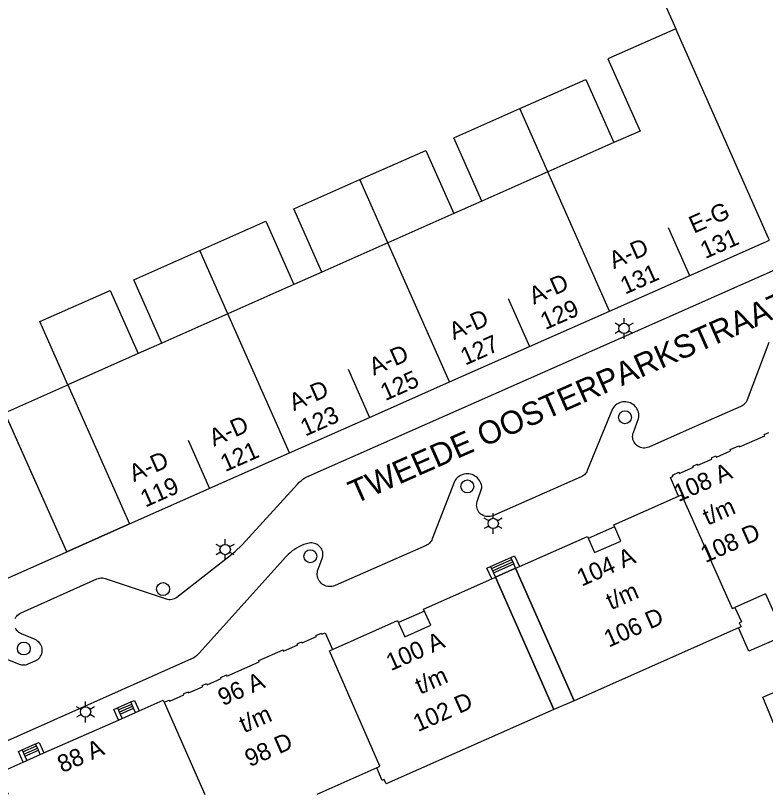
# Model space of a CAD drawing. Extents: x 122462 to 123306, y 485548 to 486417.
# Drawn here: x 122932.7 to 122997.6, y 485548.3 to 485615.8 of the extents above; entities that cross this region are included whole.
import ezdxf

# ---------------------------------------------------------------- set-up
doc = ezdxf.new("R2010")
doc.units = 0
for name, color, linetype in [('B-WE-IE-MEUBILAIR_WEGMEUBILAIR_VERKEERSBORD-S', 7, 'Continuous'), ('Level 1', 7, 'Continuous'), ('Level 10', 7, 'Continuous'), ('Level 11', 7, 'Continuous'), ('Level 17', 7, 'Continuous'), ('Level 19', 7, 'Continuous'), ('Level 21', 7, 'Continuous'), ('Level 30', 7, 'Continuous'), ('Level 31', 7, 'Continuous'), ('Level 33', 7, 'Continuous'), ('Level 4', 7, 'Continuous'), ('Level 50', 7, 'Continuous'), ('Level 53', 7, 'Continuous'), ('N werkgrens', 7, 'Continuous'), ('N-WE-AL-T25', 7, 'Continuous'), ('N-WE-GR-BOOM_DOORWORTELBARE RUIMTE-G', 7, 'Continuous')]:
    doc.layers.add(name, color=color, linetype=linetype)

msp = doc.modelspace()

# ---------------------------------------------------------------- linework, layer by layer
at = {"layer": 'Level 1'}
for p, q in [((122984.506, 485604.819), (122978.793, 485602.284)), ((122978.793, 485602.284), (122973.081, 485599.749)), ((122973.081, 485599.749), (122970.643, 485598.667)), ((122970.643, 485598.667), (122964.93, 485596.132)), ((122964.93, 485596.132), (122959.218, 485593.597)), ((122959.218, 485593.597), (122956.78, 485592.515)), ((122956.78, 485592.515), (122951.067, 485589.98)), ((122937.1, 485569.36), (122927.164, 485591.602)), ((122977.213, 485587.149), (122984.146, 485590.223)), ((122951.067, 485589.98), (122945.355, 485587.445)), ((122945.355, 485587.445), (122943.29, 485586.528)), ((122970.281, 485584.075), (122977.213, 485587.149)), ((122943.29, 485586.528), (122937.204, 485583.828)), ((122963.348, 485581), (122970.281, 485584.075)), ((122937.204, 485583.828), (122942.551, 485571.778)), ((122956.416, 485577.926), (122963.348, 485581)), ((122942.551, 485571.778), (122956.416, 485577.926)), ((122976.004, 485567.929), (122976.324, 485568.071)), ((122973.927, 485567.007), (122974.246, 485567.148)), ((122997.667, 485565.71), (122995.013, 485564.536)), ((122941.573, 485554.763), (122941.895, 485554.905)), ((122941.895, 485554.905), (122943.056, 485555.417)), ((122943.056, 485555.417), (122943.376, 485555.558)), ((122935.122, 485551.92), (122941.573, 485554.763)), ((122933.632, 485551.263), (122934.802, 485551.779)), ((122934.802, 485551.779), (122935.122, 485551.92)), ((122933.311, 485551.122), (122933.632, 485551.263)), ((122963.964, 485550.622), (122958.766, 485548.322))]:
    msp.add_line(p, q, dxfattribs=at)
for points in [[(122990.902, 485617.994), (122988.827, 485617.071), (122989.883, 485614.69)], [(122989.883, 485614.69), (122984.006, 485612.082), (122986.781, 485605.829), (122984.506, 485604.819)], [(122984.146, 485590.223), (122987.657, 485591.78), (122998.009, 485596.37), (122997.93, 485596.553)], [(122915.14, 485586.229), (122925.07, 485563.999), (122937.1, 485569.36)], [(122990.12, 485574.189), (122989.41, 485575.799), (122989.655, 485575.91), (122989.61, 485576.009), (122990.143, 485576.246), (122990.187, 485576.146), (122991.414, 485576.688), (122991.37, 485576.788), (122991.745, 485576.954), (122991.789, 485576.853), (122993.016, 485577.395), (122992.972, 485577.496), (122993.366, 485577.67), (122993.41, 485577.569), (122994.632, 485578.109), (122994.588, 485578.21), (122995.357, 485578.55), (122995.401, 485578.449), (122997.588, 485579.415), (122997.544, 485579.516), (122997.939, 485579.689)], [(122976.324, 485568.071), (122982.222, 485570.687), (122982.847, 485569.28), (122985.12, 485570.288), (122984.499, 485571.679), (122990.12, 485574.189)], [(122995.326, 485562.749), (122981.084, 485556.447), (122976.004, 485567.929)], [(122974.246, 485567.148), (122979.325, 485555.669), (122964.777, 485549.232), (122964.607, 485549.616), (122964.442, 485549.543), (122963.964, 485550.622)], [(122960.142, 485560.892), (122965.775, 485563.39), (122966.391, 485561.989), (122968.651, 485562.982), (122968.029, 485564.39), (122973.927, 485567.007)], [(122995.013, 485564.536), (122995.567, 485563.283), (122995.384, 485563.202), (122995.542, 485562.845), (122995.326, 485562.749)], [(122945.548, 485556.308), (122945.989, 485556.502), (122946.033, 485556.402), (122947.26, 485556.943), (122947.216, 485557.043), (122947.605, 485557.214), (122947.649, 485557.114), (122948.876, 485557.654), (122948.832, 485557.755), (122949.217, 485557.925), (122949.261, 485557.825), (122950.492, 485558.367), (122950.448, 485558.468), (122950.943, 485558.686), (122950.987, 485558.586), (122953.789, 485559.821), (122953.745, 485559.92), (122955.855, 485560.85), (122955.899, 485560.75), (122957.118, 485561.287), (122957.074, 485561.387), (122957.467, 485561.56), (122957.511, 485561.461), (122958.733, 485561.999), (122958.689, 485562.099), (122959.17, 485562.309), (122959.215, 485562.211), (122959.509, 485562.34), (122960.142, 485560.892)], [(123003.934, 485554.519), (122999.198, 485552.468), (122997.411, 485556.744), (123001.734, 485558.616)], [(122943.376, 485555.558), (122945.469, 485556.479), (122945.548, 485556.308)], [(122932.05, 485548.322), (122931.219, 485550.199), (122933.311, 485551.122)]]:
    msp.add_lwpolyline(points, dxfattribs=at)
at = {"layer": 'Level 10'}
for points in [[(122937.1, 485569.36), (122931.724, 485581.396), (122937.204, 485583.828), (122942.551, 485571.778), (122937.1, 485569.36)], [(122979.325, 485555.669), (122974.246, 485567.148), (122976.004, 485567.929), (122981.084, 485556.447), (122979.325, 485555.669)]]:
    msp.add_lwpolyline(points, dxfattribs=at)
at = {"layer": 'Level 11'}
for p, q in [((122984.572, 485571.522), (122982.299, 485570.514)), ((122968.107, 485564.218), (122965.848, 485563.225))]:
    msp.add_line(p, q, dxfattribs=at)
at = {"layer": 'Level 17'}
msp.add_line((122937.1, 485569.36), (122942.551, 485571.778), dxfattribs=at)
for points in [[(122940.067, 485567.092), (122940.191, 485567.091), (122940.313, 485567.074), (122940.433, 485567.042), (122945.713, 485565.275), (122945.832, 485565.243), (122945.954, 485565.226), (122946.077, 485565.224), (122946.2, 485565.238), (122946.32, 485565.266), (122946.435, 485565.309), (122946.544, 485565.365), (122946.646, 485565.435), (122951.671, 485569.361), (122952.291, 485569.961), (122957.106, 485575.228), (122957.251, 485575.376), (122957.406, 485575.514), (122957.57, 485575.64), (122957.742, 485575.755), (122957.922, 485575.858), (122958.108, 485575.948), (122988.609, 485589.427), (122998.537, 485593.815)], [(122997.939, 485587.488), (122996.081, 485582.534), (122996.031, 485582.428), (122995.971, 485582.327), (122995.9, 485582.234), (122995.82, 485582.149), (122995.731, 485582.072), (122995.634, 485582.006), (122995.531, 485581.95), (122992.224, 485580.499), (122991.032, 485579.976), (122987.543, 485578.432), (122987.427, 485578.389), (122987.307, 485578.361), (122987.184, 485578.348), (122987.061, 485578.35), (122986.939, 485578.368), (122986.82, 485578.4), (122986.705, 485578.446), (122986.598, 485578.507), (122986.498, 485578.58), (122986.409, 485578.665), (122986.331, 485578.76), (122986.264, 485578.864), (122986.212, 485578.976), (122986.173, 485579.093), (122986.149, 485579.214), (122986.14, 485579.337), (122986.147, 485579.461), (122986.169, 485579.582), (122986.205, 485579.7), (122986.661, 485580.911), (122986.678, 485581.047), (122986.681, 485581.183), (122986.667, 485581.319), (122986.639, 485581.453), (122986.596, 485581.583), (122986.539, 485581.707), (122986.469, 485581.824), (122986.385, 485581.932)], [(122986.385, 485581.932), (122986.291, 485582.031), (122986.185, 485582.118), (122986.071, 485582.193), (122985.949, 485582.255), (122985.821, 485582.302), (122985.689, 485582.336), (122985.553, 485582.354), (122985.417, 485582.357), (122985.28, 485582.345), (122985.147, 485582.317), (122985.017, 485582.275), (122984.892, 485582.219), (122984.775, 485582.149), (122984.666, 485582.067), (122984.567, 485581.972), (122984.479, 485581.868), (122984.403, 485581.754), (122982.209, 485576.391), (122982.162, 485576.292), (122982.104, 485576.199), (122982.037, 485576.113), (122981.96, 485576.034), (122981.875, 485575.965), (122981.784, 485575.905), (122981.686, 485575.855), (122974.028, 485572.484), (122973.914, 485572.442), (122973.795, 485572.414), (122973.674, 485572.4), (122973.552, 485572.402), (122973.431, 485572.418), (122973.313, 485572.449), (122973.199, 485572.494), (122973.092, 485572.553), (122972.993, 485572.624), (122972.904, 485572.706), (122972.825, 485572.799), (122972.757, 485572.901), (122972.703, 485573.01), (122972.663, 485573.125), (122972.636, 485573.245), (122972.625, 485573.366), (122972.628, 485573.488), (122972.646, 485573.608), (122972.679, 485573.726), (122973.081, 485574.891), (122973.068, 485575.029), (122973.04, 485575.164), (122972.998, 485575.295), (122972.941, 485575.421), (122972.872, 485575.541), (122972.789, 485575.652), (122972.696, 485575.753), (122972.591, 485575.844), (122972.478, 485575.922), (122972.357, 485575.988), (122972.229, 485576.041), (122972.096, 485576.079), (122971.96, 485576.103), (122971.822, 485576.111), (122971.684, 485576.105), (122971.548, 485576.084), (122971.414, 485576.048), (122971.286, 485575.998), (122971.163, 485575.934), (122971.048, 485575.857), (122970.943, 485575.768), (122970.847, 485575.669), (122970.763, 485575.559), (122970.691, 485575.441), (122968.775, 485570.465), (122968.729, 485570.363), (122968.671, 485570.266), (122968.603, 485570.176), (122968.525, 485570.095), (122968.439, 485570.023), (122968.345, 485569.961), (122968.245, 485569.91), (122960.352, 485566.431), (122960.231, 485566.386), (122960.105, 485566.355), (122959.976, 485566.34), (122959.847, 485566.339), (122959.718, 485566.354), (122959.592, 485566.384), (122959.471, 485566.429), (122959.355, 485566.487), (122959.247, 485566.559), (122959.149, 485566.642), (122959.061, 485566.737), (122958.984, 485566.842), (122958.921, 485566.955), (122958.871, 485567.074), (122958.835, 485567.198), (122958.814, 485567.326), (122958.809, 485567.456), (122958.819, 485567.585), (122958.843, 485567.712), (122958.883, 485567.835), (122959.24, 485568.759)], [(122959.24, 485568.759), (122959.276, 485568.873), (122959.299, 485568.99), (122959.308, 485569.109), (122959.302, 485569.229), (122959.282, 485569.346), (122959.248, 485569.461), (122959.201, 485569.571), (122959.14, 485569.674), (122959.069, 485569.769), (122958.986, 485569.855), (122958.893, 485569.931), (122958.792, 485569.995), (122958.685, 485570.047), (122958.571, 485570.085), (122958.455, 485570.109), (122958.336, 485570.12), (122958.216, 485570.116), (122958.098, 485570.098), (122957.873, 485570.042), (122957.653, 485569.972), (122957.437, 485569.889), (122957.227, 485569.792), (122957.023, 485569.681), (122956.827, 485569.559), (122956.639, 485569.423), (122956.46, 485569.277), (122956.29, 485569.119), (122956.131, 485568.951), (122948.577, 485560.561), (122948.46, 485560.441), (122948.333, 485560.332), (122948.198, 485560.234), (122948.055, 485560.147), (122947.905, 485560.072), (122926.951, 485550.731)], [(122932.638, 485563.565), (122932.694, 485563.674), (122932.763, 485563.775), (122932.844, 485563.867), (122932.936, 485563.948), (122933.036, 485564.017), (122933.145, 485564.074), (122939.708, 485567.006), (122939.824, 485567.05), (122939.944, 485567.079), (122940.067, 485567.092)], [(122928.201, 485561.532), (122932.979, 485559.619), (122933.085, 485559.583), (122933.195, 485559.56), (122933.307, 485559.549), (122933.419, 485559.55), (122933.53, 485559.564), (122933.639, 485559.59), (122933.745, 485559.628), (122934.374, 485559.898), (122934.484, 485559.953), (122934.586, 485560.022), (122934.68, 485560.103), (122934.762, 485560.194), (122934.833, 485560.295), (122934.891, 485560.404), (122934.935, 485560.519), (122934.964, 485560.639), (122934.979, 485560.761), (122934.978, 485560.884), (122934.962, 485561.007), (122934.931, 485561.126), (122934.886, 485561.241), (122934.827, 485561.349), (122934.755, 485561.449), (122934.672, 485561.54), (122934.578, 485561.619), (122934.475, 485561.687), (122934.364, 485561.741), (122933.17, 485562.238), (122933.06, 485562.292), (122932.957, 485562.358), (122932.864, 485562.437), (122932.78, 485562.527), (122932.708, 485562.626), (122932.649, 485562.733)]]:
    msp.add_lwpolyline(points, dxfattribs=at)
at = {"layer": 'Level 19'}
for p, q in [((122978.793, 485602.284), (122976.359, 485607.769)), ((122964.93, 485596.132), (122962.496, 485601.617)), ((122951.067, 485589.98), (122948.633, 485595.465))]:
    msp.add_line(p, q, dxfattribs=at)
msp.add_lwpolyline([(122997.667, 485565.71), (122999.272, 485562.08), (122996.22, 485560.729), (122995.326, 485562.749)], dxfattribs=at)
at = {"layer": 'Level 21'}
for p, q in [((122975.837, 485568.305), (122975.594, 485568.853)), ((122973.836, 485568.072), (122974.079, 485567.524)), ((122976.004, 485567.929), (122975.837, 485568.305)), ((122974.079, 485567.524), (122974.246, 485567.148)), ((122942.895, 485555.785), (122942.653, 485556.334)), ((122941.491, 485555.821), (122941.733, 485555.272)), ((122943.056, 485555.417), (122942.895, 485555.785)), ((122941.733, 485555.272), (122941.895, 485554.905)), ((122934.64, 485552.146), (122934.398, 485552.695)), ((122933.228, 485552.18), (122933.47, 485551.631)), ((122933.47, 485551.631), (122933.632, 485551.263)), ((122934.802, 485551.779), (122934.64, 485552.146))]:
    msp.add_line(p, q, dxfattribs=at)
for points in [[(122975.594, 485568.853), (122975.914, 485568.995), (122976.324, 485568.071)], [(122973.927, 485567.007), (122973.517, 485567.931), (122973.836, 485568.072)], [(122942.653, 485556.334), (122942.973, 485556.474), (122943.376, 485555.558)], [(122941.573, 485554.763), (122941.17, 485555.679), (122941.491, 485555.821)], [(122934.398, 485552.695), (122934.718, 485552.836), (122935.122, 485551.92)], [(122933.311, 485551.122), (122932.907, 485552.038), (122933.228, 485552.18)]]:
    msp.add_lwpolyline(points, dxfattribs=at)
at = {"layer": 'Level 30'}
for p, q in [((122974.079, 485567.524), (122975.837, 485568.305)), ((122976.004, 485567.929), (122974.246, 485567.148)), ((122941.733, 485555.272), (122942.895, 485555.785)), ((122933.47, 485551.631), (122934.64, 485552.146))]:
    msp.add_line(p, q, dxfattribs=at)
at = {"layer": 'Level 31'}
for p, q in [((122973.836, 485568.072), (122975.594, 485568.853)), ((122941.491, 485555.821), (122942.653, 485556.334)), ((122933.228, 485552.18), (122934.398, 485552.695))]:
    msp.add_line(p, q, dxfattribs=at)
at = {"layer": 'Level 33'}
for p, q in [((122973.913, 485567.899), (122975.671, 485568.68)), ((122973.996, 485567.711), (122975.754, 485568.492)), ((122941.568, 485555.647), (122942.73, 485556.16)), ((122941.65, 485555.46), (122942.812, 485555.973)), ((122933.305, 485552.006), (122934.475, 485552.521)), ((122933.387, 485551.819), (122934.557, 485552.334))]:
    msp.add_line(p, q, dxfattribs=at)
at = {"layer": 'Level 4'}
for p, q in [((122997.93, 485596.553), (122989.883, 485614.69)), ((122984.146, 485590.223), (122978.793, 485602.284)), ((122970.281, 485584.075), (122964.93, 485596.132)), ((122956.416, 485577.926), (122951.067, 485589.98)), ((122945.548, 485556.308), (122949.067, 485548.322))]:
    msp.add_line(p, q, dxfattribs=at)
for points in [[(122990.12, 485574.189), (122990.377, 485574.305), (122994.761, 485564.424), (122995.013, 485564.536)], [(122963.964, 485550.622), (122964.247, 485550.781), (122959.86, 485560.767), (122960.142, 485560.892)]]:
    msp.add_lwpolyline(points, dxfattribs=at)
at = {"layer": 'Level 50'}
for p, q in [((122985.4, 485589.169), (122985.4, 485589.619)), ((122985.01, 485588.944), (122984.62, 485589.169)), ((122986.179, 485589.169), (122985.789, 485588.944)), ((122985.01, 485588.494), (122984.62, 485588.269)), ((122985.4, 485587.819), (122985.4, 485588.269)), ((122986.179, 485588.269), (122985.789, 485588.494)), ((122974.06, 485572.259), (122974.06, 485572.709)), ((122973.67, 485572.034), (122973.28, 485572.259)), ((122974.839, 485572.259), (122974.449, 485572.034)), ((122973.67, 485571.584), (122973.28, 485571.359)), ((122974.06, 485570.909), (122974.06, 485571.359)), ((122974.839, 485571.359), (122974.449, 485571.584)), ((122950.83, 485569.999), (122950.83, 485570.449)), ((122950.44, 485569.774), (122950.05, 485569.999)), ((122951.609, 485569.999), (122951.219, 485569.774)), ((122950.44, 485569.324), (122950.05, 485569.099)), ((122950.83, 485568.649), (122950.83, 485569.099)), ((122951.609, 485569.099), (122951.219, 485569.324)), ((122938.73, 485555.919), (122938.73, 485556.369)), ((122938.34, 485555.694), (122937.95, 485555.919)), ((122939.509, 485555.919), (122939.119, 485555.694)), ((122938.34, 485555.244), (122937.95, 485555.019)), ((122938.73, 485554.569), (122938.73, 485555.019)), ((122939.509, 485555.019), (122939.119, 485555.244))]:
    msp.add_line(p, q, dxfattribs=at)
for centre in [(122985.4, 485588.719), (122974.06, 485571.809), (122950.83, 485569.549), (122938.73, 485555.469)]:
    msp.add_circle(centre, 0.45, dxfattribs=at)
at = {"layer": 'Level 53'}
for centre in [(122985.48, 485581.019), (122971.82, 485575.019), (122958.21, 485568.969), (122945.45, 485566.119), (122933.38, 485560.969)]:
    msp.add_circle(centre, 0.56, dxfattribs=at)
at = {"layer": 'N werkgrens'}
for points in [[(122976.359, 485607.769), (122982.072, 485610.304), (122984.506, 485604.819)], [(122973.081, 485599.749), (122970.647, 485605.234), (122976.359, 485607.769)], [(122962.496, 485601.617), (122968.209, 485604.152), (122970.643, 485598.667)], [(122959.218, 485593.597), (122956.784, 485599.082), (122962.496, 485601.617)], [(122948.633, 485595.465), (122954.346, 485598), (122956.78, 485592.515)], [(122945.355, 485587.445), (122942.921, 485592.93), (122948.633, 485595.465)], [(122937.204, 485583.828), (122934.771, 485589.313), (122940.857, 485592.014), (122943.29, 485586.528)]]:
    msp.add_lwpolyline(points, dxfattribs=at)
at = {"layer": 'N-WE-AL-T25'}
for p, q in [((122989.224, 485597.474), (122991.078, 485593.297)), ((122975.361, 485591.323), (122977.213, 485587.149)), ((122977.213, 485587.149), (122977.213, 485587.148)), ((122961.497, 485585.171), (122963.348, 485581)), ((122947.634, 485579.018), (122949.483, 485574.852))]:
    msp.add_line(p, q, dxfattribs=at)

# ---------------------------------------------------------------- texts
at = {"layer": 'B-WE-IE-MEUBILAIR_WEGMEUBILAIR_VERKEERSBORD-S'}
for s, rotation, p in [('E-G', 23.93199, (122991.446, 485596.917)), ('131', 23.93199, (122992.43, 485594.719)), ('A-D', 23.93199, (122984.513, 485593.841)), ('131', 23.93199, (122985.498, 485591.642)), ('A-D', 23.93199, (122977.581, 485590.764)), ('129', 23.93199, (122978.569, 485588.565)), ('A-D', 23.93199, (122970.649, 485587.687)), ('127', 23.93199, (122971.636, 485585.488)), ('A-D', 23.93199, (122963.717, 485584.61)), ('125', 23.93199, (122964.704, 485582.411)), ('A-D', 23.93199, (122956.785, 485581.533)), ('123', 23.93199, (122957.773, 485579.334)), ('A-D', 23.93199, (122949.853, 485578.456)), ('121', 23.93199, (122950.838, 485576.257)), ('A-D', 23.93199, (122942.921, 485575.379)), ('108 A', 23.83091, (122990.112, 485573.652)), ('119', 23.93199, (122943.908, 485573.179)), ('t/m', 23.83091, (122992.642, 485571.612)), ('108 D', 23.83091, (122992.448, 485568.366)), ('104 A', 23.89859, (122981.731, 485566.326)), ('t/m', 23.89859, (122984.263, 485564.287)), ('106 D', 23.89859, (122984.073, 485561.041)), ('100 A', 23.89859, (122965.196, 485559)), ('t/m', 23.89859, (122967.728, 485556.961)), ('96 A', 23.77955, (122950.621, 485555.965)), ('102 D', 23.89859, (122967.539, 485553.715)), ('t/m', 23.77955, (122952.466, 485553.621)), ('98 D', 23.77955, (122952.952, 485550.677)), ('88 A', 23.78317, (122936.71, 485550.162))]:
    msp.add_text(s, height=1.5, rotation=rotation, dxfattribs=at).set_placement(p)
at = {"layer": 'N-WE-GR-BOOM_DOORWORTELBARE RUIMTE-G'}
msp.add_text('TWEEDE OOSTERPARKSTRAAT', height=2, rotation=23.83508, dxfattribs=at).set_placement((122962.082, 485573.487))

doc.saveas('drawing.dxf')
